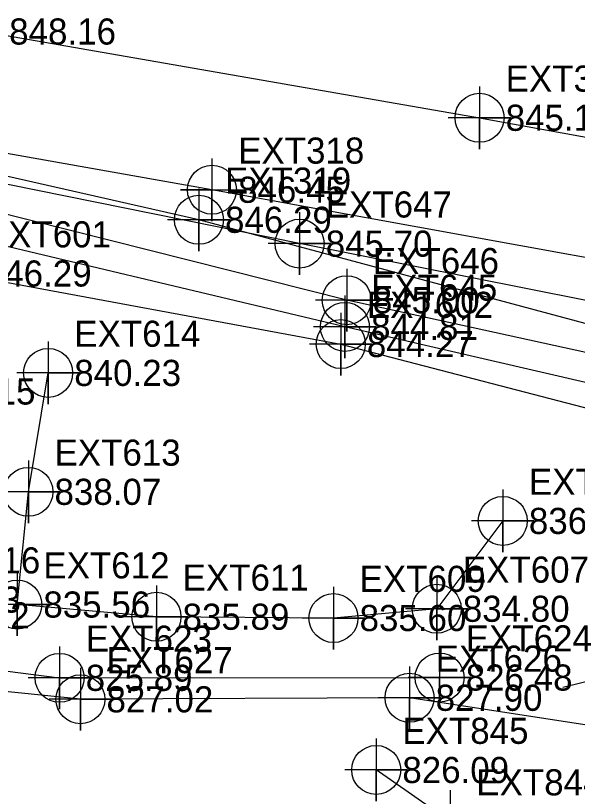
# Model space of a CAD drawing. Extents: x 1762120 to 1766775, y 709485 to 712965.
# Drawn here: x 1762910.4 to 1762964.2, y 712542.6 to 712617.4 of the extents above; entities that cross this region are included whole.
import ezdxf

# ---------------------------------------------------------------- set-up
doc = ezdxf.new("R2010")
doc.units = 0
for name, color, linetype in [('Exist DTM Breakline', 7, 'Continuous'), ('Exist DTM Breakline Cogo Elevation', 7, 'Continuous'), ('Exist DTM Breakline Cogo Number', 7, 'Continuous'), ('Exist DTM Breakline Cogo Point CELL', 7, 'Continuous'), ('Exist DTM Crownline', 7, 'Continuous'), ('Exist DTM Crownline Cogo Elevation', 7, 'Continuous'), ('Exist DTM Crownline Cogo Number', 7, 'Continuous'), ('Exist DTM Crownline Cogo Point CELL', 7, 'Continuous'), ('Exist DTM Drainline', 7, 'Continuous'), ('Exist DTM Drainline Cogo Elevation', 7, 'Continuous'), ('Exist DTM Drainline Cogo Number', 7, 'Continuous'), ('Exist DTM Drainline Cogo Point CELL', 7, 'Continuous'), ('Exist Roads EOP', 7, 'Continuous'), ('Exist Roads EOP Cogo Elevation', 7, 'Continuous'), ('Exist Roads EOP Cogo Number', 7, 'Continuous'), ('Exist Roads EOP Cogo Point CELL', 7, 'Continuous'), ('Exist Roads EOT', 7, 'Continuous'), ('Exist Roads EOT Cogo Elevation', 7, 'Continuous'), ('Exist Roads EOT Cogo Number', 7, 'Continuous'), ('Exist Roads EOT Cogo Point CELL', 7, 'Continuous'), ('Exist Utilities Telephone UG FO SUE LOS C', 7, 'Continuous'), ('Exist Utilities Telephone UG FO SUE LOS C Cogo Elevation', 7, 'Continuous'), ('Exist Utilities Telephone UG FO SUE LOS C Cogo Number', 7, 'Continuous'), ('Exist Utilities Telephone UG FO SUE LOS C Cogo Point CELL', 7, 'Continuous'), ('Exist Utilities Water UG Line SUE LOS C', 7, 'Continuous'), ('Exist Utilities Water UG Line SUE LOS C Cogo Elevation', 7, 'Continuous'), ('Exist Utilities Water UG Line SUE LOS C Cogo Number', 7, 'Continuous'), ('Exist Utilities Water UG Line SUE LOS C Cogo Point CELL', 7, 'Continuous')]:
    doc.layers.add(name, color=color, linetype=linetype)

msp = doc.modelspace()

# ---------------------------------------------------------------- linework, layer by layer
at = {"layer": 'Exist DTM Breakline'}
for points in [[(1762719.497, 712557.512), (1762723.372, 712579.212), (1762728.166, 712592.081), (1762719.687, 712602.684), (1762720.676, 712608.523), (1762728.459, 712607.703), (1762735.491, 712603.427), (1762739.908, 712614.078), (1762743.864, 712621.238), (1762758.622, 712619.916), (1762767.954, 712615.272), (1762785.326, 712612.968), (1762818.774, 712608.043), (1762844.339, 712603.197), (1762875.474, 712595.472), (1762904.983, 712592.7), (1762941.56, 712585.948), (1762969.552, 712578.669)], [(1762957.067, 712569.012), (1762950.742, 712560.602), (1762940.86, 712559.716), (1762923.916, 712559.837), (1762910.59, 712561.007), (1762911.654, 712571.798), (1762913.548, 712583.183)], [(1762962.802, 712553.103), (1762972.335, 712555.417), (1762981.953, 712555.52), (1762994.971, 712555.687), (1763023.336, 712551.42), (1763039.477, 712550.099), (1763044.177, 712551.535), (1763048.383, 712551.819), (1763050.625, 712549.373), (1763055.79, 712554.626), (1763058.948, 712552.999), (1763061.353, 712555.311)], [(1762967.817, 712549.031), (1762948.142, 712552.079), (1762916.634, 712551.933), (1762895.251, 712554.117), (1762880.506, 712555.136), (1762869.37, 712546.084), (1762870.084, 712532.353), (1762872.621, 712514.941)], [(1762969.974, 712535.636), (1762952.031, 712540.235), (1762944.953, 712545.168)]]:
    msp.add_lwpolyline(points, dxfattribs=at)
at = {"layer": 'Exist DTM Breakline Cogo Point CELL'}
for points in [[(1762941.56, 712588.948), (1762941.56, 712582.948), (1762941.56, 712585.948), (1762944.56, 712585.948), (1762938.56, 712585.948)], [(1762913.548, 712586.183), (1762913.548, 712580.183), (1762913.548, 712583.183), (1762916.548, 712583.183), (1762910.548, 712583.183)], [(1762911.654, 712574.798), (1762911.654, 712568.798), (1762911.654, 712571.798), (1762914.654, 712571.798), (1762908.654, 712571.798)], [(1762957.067, 712572.012), (1762957.067, 712566.012), (1762957.067, 712569.012), (1762960.067, 712569.012), (1762954.067, 712569.012)], [(1762910.59, 712564.007), (1762910.59, 712558.007), (1762910.59, 712561.007), (1762913.59, 712561.007), (1762907.59, 712561.007)], [(1762950.742, 712563.602), (1762950.742, 712557.602), (1762950.742, 712560.602), (1762953.742, 712560.602), (1762947.742, 712560.602)], [(1762923.916, 712562.837), (1762923.916, 712556.837), (1762923.916, 712559.837), (1762926.916, 712559.837), (1762920.916, 712559.837)], [(1762940.86, 712562.716), (1762940.86, 712556.716), (1762940.86, 712559.716), (1762943.86, 712559.716), (1762937.86, 712559.716)], [(1762916.634, 712554.933), (1762916.634, 712548.933), (1762916.634, 712551.933), (1762919.634, 712551.933), (1762913.634, 712551.933)], [(1762948.142, 712555.079), (1762948.142, 712549.079), (1762948.142, 712552.079), (1762951.142, 712552.079), (1762945.142, 712552.079)], [(1762944.953, 712548.168), (1762944.953, 712542.168), (1762944.953, 712545.168), (1762947.953, 712545.168), (1762941.953, 712545.168)], [(1762952.031, 712543.235), (1762952.031, 712537.235), (1762952.031, 712540.235), (1762955.031, 712540.235), (1762949.031, 712540.235)]]:
    msp.add_lwpolyline(points, dxfattribs=at)
for centre in [(1762941.56, 712585.948), (1762913.548, 712583.183), (1762911.654, 712571.798), (1762957.067, 712569.012), (1762910.59, 712561.007), (1762950.742, 712560.602), (1762923.916, 712559.837), (1762940.86, 712559.716), (1762916.634, 712551.933), (1762948.142, 712552.079), (1762944.953, 712545.168)]:
    msp.add_circle(centre, 2.344, dxfattribs=at)
at = {"layer": 'Exist DTM Crownline'}
msp.add_lwpolyline([(1762166.547, 712774.687), (1762217.293, 712763.929), (1762266.928, 712753.164), (1762315.989, 712742.645), (1762361.304, 712733.127), (1762409.518, 712722.711), (1762461.505, 712711.505), (1762512.117, 712700.307), (1762561.004, 712689.861), (1762611.478, 712678.845), (1762663.765, 712667.96), (1762715.266, 712656.972), (1762767.733, 712645.753), (1762820.16, 712634.416), (1762873.558, 712623.116), (1762907.318, 712615.867), (1762954.844, 712607.608), (1762970.656, 712604.722)], dxfattribs=at)
at = {"layer": 'Exist DTM Crownline Cogo Point CELL'}
msp.add_lwpolyline([(1762954.844, 712610.608), (1762954.844, 712604.608), (1762954.844, 712607.608), (1762957.844, 712607.608), (1762951.844, 712607.608)], dxfattribs=at)
msp.add_circle((1762954.844, 712607.608), 2.344, dxfattribs=at)
at = {"layer": 'Exist DTM Drainline'}
msp.add_lwpolyline([(1762866.599, 712549.079), (1762881.735, 712557.699), (1762897.192, 712556.215), (1762914.644, 712553.99), (1762951.022, 712554.017)], dxfattribs=at)
at = {"layer": 'Exist DTM Drainline Cogo Point CELL'}
for points in [[(1762914.644, 712556.99), (1762914.644, 712550.99), (1762914.644, 712553.99), (1762917.644, 712553.99), (1762911.644, 712553.99)], [(1762951.022, 712557.017), (1762951.022, 712551.017), (1762951.022, 712554.017), (1762954.022, 712554.017), (1762948.022, 712554.017)]]:
    msp.add_lwpolyline(points, dxfattribs=at)
for centre in [(1762914.644, 712553.99), (1762951.022, 712554.017)]:
    msp.add_circle(centre, 2.344, dxfattribs=at)
at = {"layer": 'Exist Roads EOP'}
msp.add_lwpolyline([(1762974.578, 712585.314), (1762927.979, 712597.842), (1762890.673, 712606.296), (1762842.51, 712617.09), (1762793.23, 712628.151), (1762744.7, 712638.794), (1762696.334, 712649.071), (1762645.671, 712659.578), (1762597.313, 712669.972), (1762548.878, 712680.543), (1762499.868, 712691.039), (1762451.782, 712701.31), (1762402.083, 712712.161), (1762353.635, 712722.593), (1762304.798, 712733.112), (1762255.134, 712743.654), (1762207.339, 712753.911), (1762164.278, 712763.059), (1762150.692, 712765.782)], dxfattribs=at)
at = {"layer": 'Exist Roads EOP Cogo Point CELL'}
msp.add_lwpolyline([(1762927.979, 712600.842), (1762927.979, 712594.842), (1762927.979, 712597.842), (1762930.979, 712597.842), (1762924.979, 712597.842)], dxfattribs=at)
msp.add_circle((1762927.979, 712597.842), 2.344, dxfattribs=at)
at = {"layer": 'Exist Roads EOT'}
msp.add_lwpolyline([(1762968.661, 712593.549), (1762929.231, 712600.717), (1762891.559, 712607.395)], dxfattribs=at)
at = {"layer": 'Exist Roads EOT Cogo Point CELL'}
msp.add_lwpolyline([(1762929.231, 712603.717), (1762929.231, 712597.717), (1762929.231, 712600.717), (1762926.231, 712600.717), (1762932.231, 712600.717)], dxfattribs=at)
msp.add_circle((1762929.231, 712600.717), 2.344, dxfattribs=at)
at = {"layer": 'Exist Utilities Telephone UG FO SUE LOS C'}
for points in [[(1762975.06, 712582.936), (1762942.128, 712590.141), (1762892.884, 712602.573), (1762845.987, 712612.29), (1762766.135, 712629.835), (1762702.526, 712643.51), (1762677.774, 712648.696)], [(1762974.378, 712580.101), (1762941.961, 712587.59), (1762882.884, 712601.621), (1762847.537, 712609.713), (1762765.896, 712628.049), (1762704.218, 712639.933), (1762682.076, 712645.625)]]:
    msp.add_lwpolyline(points, dxfattribs=at)
at = {"layer": 'Exist Utilities Telephone UG FO SUE LOS C Cogo Point CELL'}
for points in [[(1762942.128, 712593.141), (1762942.128, 712587.141), (1762942.128, 712590.141), (1762945.128, 712590.141), (1762939.128, 712590.141)], [(1762941.961, 712590.59), (1762941.961, 712584.59), (1762941.961, 712587.59), (1762944.961, 712587.59), (1762938.961, 712587.59)]]:
    msp.add_lwpolyline(points, dxfattribs=at)
for centre in [(1762942.128, 712590.141), (1762941.961, 712587.59)]:
    msp.add_circle(centre, 2.344, dxfattribs=at)
at = {"layer": 'Exist Utilities Water UG Line SUE LOS C'}
msp.add_lwpolyline([(1762975.806, 712587.967), (1762937.62, 712595.557), (1762895.763, 712604.028), (1762842.398, 712615.448), (1762766.685, 712632.078), (1762701.56, 712645.979), (1762676.599, 712651.124)], dxfattribs=at)
at = {"layer": 'Exist Utilities Water UG Line SUE LOS C Cogo Point CELL'}
msp.add_lwpolyline([(1762937.62, 712598.557), (1762937.62, 712592.557), (1762937.62, 712595.557), (1762940.62, 712595.557), (1762934.62, 712595.557)], dxfattribs=at)
msp.add_circle((1762937.62, 712595.557), 2.344, dxfattribs=at)

# ---------------------------------------------------------------- texts
at = {"layer": 'Exist DTM Breakline Cogo Elevation'}
for s, p in [('846.29', (1762907.483, 712591.45)), ('844.27', (1762944.06, 712584.698)), ('840.23', (1762916.048, 712581.933)), ('838.07', (1762914.154, 712570.548)), ('836.95', (1762959.567, 712567.762)), ('831.43', (1762900.715, 712560.233)), ('835.56', (1762913.09, 712559.757)), ('834.80', (1762953.242, 712559.352)), ('835.89', (1762926.416, 712558.587)), ('835.60', (1762943.36, 712558.466)), ('827.02', (1762919.134, 712550.683)), ('827.90', (1762950.642, 712550.829)), ('826.09', (1762947.453, 712543.918))]:
    msp.add_text(s, height=2.5, dxfattribs=at).set_placement(p)
at = {"layer": 'Exist DTM Breakline Cogo Number'}
for s, p in [('EXT601', (1762907.483, 712595.2)), ('EXT602', (1762944.06, 712588.448)), ('EXT614', (1762916.048, 712585.683)), ('EXT615', (1762900.253, 712580.153)), ('EXT613', (1762914.154, 712574.298)), ('EXT606', (1762959.567, 712571.512)), ('EXT616', (1762900.715, 712563.983)), ('EXT612', (1762913.09, 712563.507)), ('EXT607', (1762953.242, 712563.102)), ('EXT611', (1762926.416, 712562.337)), ('EXT609', (1762943.36, 712562.216)), ('EXT627', (1762919.134, 712554.433)), ('EXT626', (1762950.642, 712554.579)), ('EXT845', (1762947.453, 712547.668)), ('EXT844', (1762954.531, 712542.735))]:
    msp.add_text(s, height=2.5, dxfattribs=at).set_placement(p)
at = {"layer": 'Exist DTM Crownline Cogo Elevation'}
for s, p in [('848.16', (1762909.818, 712614.617)), ('845.19', (1762957.344, 712606.358))]:
    msp.add_text(s, height=2.5, dxfattribs=at).set_placement(p)
at = {"layer": 'Exist DTM Crownline Cogo Number'}
msp.add_text('EXT354', height=2.5, dxfattribs=at).set_placement((1762957.344, 712610.108))
at = {"layer": 'Exist DTM Drainline Cogo Elevation'}
for s, p in [('825.89', (1762917.144, 712552.74)), ('826.48', (1762953.522, 712552.767))]:
    msp.add_text(s, height=2.5, dxfattribs=at).set_placement(p)
at = {"layer": 'Exist DTM Drainline Cogo Number'}
for s, p in [('EXT622', (1762899.692, 712558.715)), ('EXT623', (1762917.144, 712556.49)), ('EXT624', (1762953.522, 712556.517))]:
    msp.add_text(s, height=2.5, dxfattribs=at).set_placement(p)
at = {"layer": 'Exist Roads EOP Cogo Elevation'}
msp.add_text('846.29', height=2.5, dxfattribs=at).set_placement((1762930.479, 712596.592))
at = {"layer": 'Exist Roads EOP Cogo Number'}
msp.add_text('EXT319', height=2.5, dxfattribs=at).set_placement((1762930.479, 712600.342))
at = {"layer": 'Exist Roads EOT Cogo Elevation'}
msp.add_text('846.45', height=2.5, dxfattribs=at).set_placement((1762931.731, 712599.467))
at = {"layer": 'Exist Roads EOT Cogo Number'}
msp.add_text('EXT318', height=2.5, dxfattribs=at).set_placement((1762931.731, 712603.217))
at = {"layer": 'Exist Utilities Telephone UG FO SUE LOS C Cogo Elevation'}
for s, p in [('845.00', (1762944.628, 712588.891)), ('844.81', (1762944.461, 712586.34))]:
    msp.add_text(s, height=2.5, dxfattribs=at).set_placement(p)
at = {"layer": 'Exist Utilities Telephone UG FO SUE LOS C Cogo Number'}
for s, p in [('EXT646', (1762944.628, 712592.641)), ('EXT645', (1762944.461, 712590.09))]:
    msp.add_text(s, height=2.5, dxfattribs=at).set_placement(p)
at = {"layer": 'Exist Utilities Water UG Line SUE LOS C Cogo Elevation'}
msp.add_text('845.70', height=2.5, dxfattribs=at).set_placement((1762940.12, 712594.307))
at = {"layer": 'Exist Utilities Water UG Line SUE LOS C Cogo Number'}
msp.add_text('EXT647', height=2.5, dxfattribs=at).set_placement((1762940.12, 712598.057))

doc.saveas('drawing.dxf')
